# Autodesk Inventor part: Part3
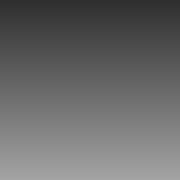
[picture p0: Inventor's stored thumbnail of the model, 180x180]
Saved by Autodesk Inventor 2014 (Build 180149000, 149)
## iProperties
Created: 2009-11
Part Number: Part3
Document SubType Name: Modeling
Designer: pokornp
Density: 1 g/cm^3
Material: Generic
Appearance: Default
Author: pokornp
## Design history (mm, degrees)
sketch "Sketch1"
  geometry: L1 (0, 0)-(2500, 0)
  constraints: 2 end point, 1 horizontal
  dimensions: "d0" = 2500 dimension on L1.start L1.end L1; "d0" = 2500 distance of L1.start L1.end
